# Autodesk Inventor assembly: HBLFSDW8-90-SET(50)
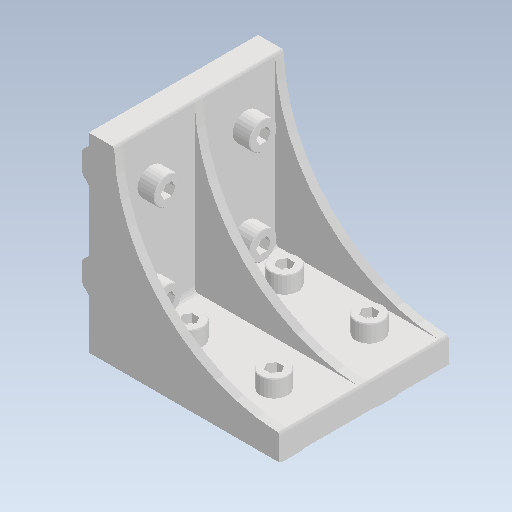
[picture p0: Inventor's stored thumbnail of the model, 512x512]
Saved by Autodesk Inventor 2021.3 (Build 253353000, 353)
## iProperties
Created: 2022-02
Part Number: HBLFSDW8-90-SET(50)
Document SubType Name: Assembly
Designer: kengo
Author: kengo
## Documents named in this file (4)
- C:\Users\kengo\Documents\S2S_frame\SDC345\frame_misumi_ver12\HBLFSDW8-90-SET(50).iam
- C:\Users\kengo\Documents\S2S_frame\SDC345\frame_misumi_ver12\HBLFSDW8-90.ipt
- C:\Users\kengo\Documents\S2S_frame\SDC345\frame_misumi_ver12\HNTT8-8.ipt
- C:\Users\kengo\Documents\S2S_frame\SDC345\frame_misumi_ver12\SCB8-22.ipt
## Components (17 placed, 3 different names)
1. HBLFSDW8-90
2. HNTT8-8
3. SCB8-22
4. HNTT8-8:1
5. SCB8-22:1
6. HNTT8-8:2
7. SCB8-22:2
8. HNTT8-8:3
9. SCB8-22:3
10. HNTT8-8:4
11. SCB8-22:4
12. HNTT8-8:5
13. SCB8-22:5
14. HNTT8-8:6
15. SCB8-22:6
16. HNTT8-8:7
17. SCB8-22:7
